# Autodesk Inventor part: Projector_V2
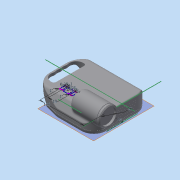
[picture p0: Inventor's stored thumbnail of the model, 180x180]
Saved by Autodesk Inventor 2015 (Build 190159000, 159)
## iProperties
Created: 2013-06
Part Number: Projector_V2
Material: 一般
Document SubType Name: Modeling
Designer: 3214325
Density: 1 g/cm^3
Appearance: Default
Author: 3214325
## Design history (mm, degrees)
sketch "Sketch1"
  geometry: L1 (66, -150)-(-66, -150); L2 (-66, -150)-(-66, 0); L3 (-66, 0)-(66, 0); L4 (66, 0)-(66, -150); L5 (92.4, 0)-(-92.4, 0) reference; L6 (0, -180)-(0, 30) reference; 1 further point
  constraints: 8 end point, 2 parallel, 1 collinear, 1 horizontal, 1 perpendicular, 1 other
  dimensions: "d0" = 132 distance of L2.end L3.end; "d1" = 150 distance of L1.end L2.end
extrude "Extrusion1" new body sketch "Sketch1" distance "d2" = 2; taper "d3" = 0 deg
sketch "Sketch2"
  geometry: L1 (66, -150)-(-66, -150) reference; L2 (66, 0)-(66, -150) reference; L3 (-66, 0)-(66, 0) reference; L4 (-66, -150)-(-66, 0) reference; L5 (92.4, 0)-(-92.4, 0) reference; L6 (-66, -88)-(-49.387, -150); L7 (0, -180)-(0, 30) reference; L8 (66, -88)-(49.387, -150); L9 (-66, -88)-(-66, -150); L10 (-66, -150)-(-49.387, -150); L11 (49.387, -150)-(66, -150); L12 (66, -150)-(66, -88); 1 further point
  constraints: 12 end point, 4 point on line, 2 horizontal, 2 vertical
  dimensions: "d4" = 88 distance from line of L6.start L5; "d5" = 15 deg angle of L6 L4; "d7" = 88 distance from line of L8.start L5; "d8" = 15 deg angle of L8 L2
extrude "Extrusion2" cut sketch "Sketch2" distance "d9" = 2; taper "d10" = 0 deg
fillet "Fillet1" dims "d11" = 30
fillet "Fillet2" dims "d12" = 30
fillet "Fillet3" dims "d13" = 40
sketch "Sketch3"
  geometry: L1 (-18.694, -150)-(18.694, -150) reference; L2 (57.331, -120.353)-(64.978, -91.815) reference; L3 (66, -84.05)-(66, -30) reference; L4 (36, 0)-(-36, 0) reference; L5 (-66, -30)-(-66, -84.05) reference; L6 (-64.978, -91.815)-(-57.331, -120.353) reference; A1 r 40 centre (-18.694, -110) between (-57.331, -120.353) and (-18.694, -150) reference; A2 r 40 centre (18.694, -110) between (18.694, -150) and (57.331, -120.353) reference; A3 r 30 centre (36, -84.05) between (64.978, -91.815) and (66, -84.05) reference; A4 r 30 centre (36, -30) between (66, -30) and (36, 0) reference; A5 r 30 centre (-36, -30) between (-36, 0) and (-66, -30) reference; A6 r 30 centre (-36, -84.05) between (-66, -84.05) and (-64.978, -91.815) reference; 1 further point
extrude "Extrusion3" join sketch "Sketch3" distance "d14" = 5; taper "d15" = -10 deg
sketch "Sketch4"
  geometry: L1 (-18.694, 150)-(18.694, 150) reference; L2 (-27, 145)-(27, 145); L3 (33, 139)-(33, 128); L4 (27, 122)-(-27, 122); L5 (-33, 128)-(-33, 139); L6 (0, 180)-(0, -30) reference; A1 r 6 centre (-27, 139) between (-27, 145) and (-33, 139); A2 r 6 centre (-27, 128) between (-33, 128) and (-27, 122); A3 r 6 centre (27, 128) between (27, 122) and (33, 128); A4 r 6 centre (27, 139) between (33, 139) and (27, 145); 4 further points
  constraints: 8 end point, 8 point on circle, 8 tangent, 6 point on line, 4 centre point, 3 equal radius, 2 parallel, 1 horizontal, 1 perpendicular, 1 other
  dimensions: "d16" = 66 distance of point (33, 122) point (-33, 122); "d17" = 23 distance of point (33, 145) point (33, 122); "d18" = 5 distance between parallel lines of L2 L1; "d19" = 6 radius of A1
extrude "Extrusion4" cut sketch "Sketch4" distance "d20" = 15; taper "d21" = 0 deg
sketch "Sketch5"
  geometry: L1 (-33, 128)-(-33, 139) reference; L2 (-27, 145)-(27, 145) reference; L3 (33, 139)-(33, 128) reference; L4 (27, 122)-(-27, 122) reference; L5 (-57.331, 120.353)-(-64.978, 91.815) reference; L6 (-66, 30)-(-66, 84.05) reference; L7 (36, 0)-(-36, 0) reference; L8 (66, 84.05)-(66, 30) reference; L9 (64.978, 91.815)-(57.331, 120.353) reference; L10 (-18.694, 150)-(18.694, 150) reference; L11 (56.365, 120.094)-(64.012, 91.556); L12 (65, 84.05)-(65, 30); L13 (36, 1)-(-36, 1); L14 (-65, 30)-(-65, 84.05); L15 (-64.012, 91.556)-(-56.365, 120.094); L16 (-18.694, 149)-(18.694, 149); A1 r 6 centre (-27, 128) between (-33, 128) and (-27, 122) reference; A2 r 6 centre (-27, 139) between (-27, 145) and (-33, 139) reference; A3 r 6 centre (27, 139) between (33, 139) and (27, 145) reference; A4 r 6 centre (27, 128) between (27, 122) and (33, 128) reference; A5 r 40 centre (-18.694, 110) between (-18.694, 150) and (-57.331, 120.353) reference; A6 r 30 centre (-36, 84.05) between (-64.978, 91.815) and (-66, 84.05) reference; A7 r 30 centre (-36, 30) between (-66, 30) and (-36, 0) reference; A8 r 30 centre (36, 30) between (36, 0) and (66, 30) reference; A9 r 30 centre (36, 84.05) between (66, 84.05) and (64.978, 91.815) reference; A10 r 40 centre (18.694, 110) between (57.331, 120.353) and (18.694, 150) reference; A11 r 39 centre (18.694, 110) between (56.365, 120.094) and (18.694, 149); A12 r 29 centre (36, 84.05) between (65, 84.05) and (64.012, 91.556); A13 r 29 centre (36, 30) between (36, 1) and (65, 30); A14 r 29 centre (-36, 30) between (-65, 30) and (-36, 1); A15 r 29 centre (-36, 84.05) between (-64.012, 91.556) and (-65, 84.05); A16 r 39 centre (-18.694, 110) between (-18.694, 149) and (-56.365, 120.094); 1 further point
  constraints: 12 end point, 12 point on circle, 6 centre point, 11 other
  dimensions: "d28" = 1 distance between parallel lines of L8 L12
extrude "Extrusion5" join sketch "Sketch5" distance "d22" = 0.3; taper "d23" = 0 deg
sketch "Sketch6"
  geometry: L1 (-33, 128)-(-33, 139) reference; L2 (-27, 145)-(27, 145) reference; L3 (33, 139)-(33, 128) reference; L4 (27, 122)-(-27, 122) reference; L5 (18.694, 149)-(-18.694, 149) reference; L6 (-56.365, 120.094)-(-64.012, 91.556) reference; L7 (-65, 84.05)-(-65, 30) reference; L8 (-36, 1)-(36, 1) reference; L9 (65, 30)-(65, 84.05) reference; L10 (64.012, 91.556)-(56.365, 120.094) reference; L11 (0, 206.201)-(0, -40.207) reference; L12 (-99.409, 0)-(99.409, 0) reference; L13 (-39, 171)-(39, 171); L14 (39, 171)-(39, 121); L15 (39, 121)-(-39, 121); L16 (-39, 121)-(-39, 171); A1 r 6 centre (-27, 139) between (-27, 145) and (-33, 139) reference; A2 r 6 centre (27, 139) between (33, 139) and (27, 145) reference; A3 r 6 centre (27, 128) between (27, 122) and (33, 128) reference; A4 r 6 centre (-27, 128) between (-33, 128) and (-27, 122) reference; A5 r 39 centre (18.694, 110) between (56.365, 120.094) and (18.694, 149) reference; A6 r 39 centre (-18.694, 110) between (-18.694, 149) and (-56.365, 120.094) reference; A7 r 29 centre (-36, 84.05) between (-64.012, 91.556) and (-65, 84.05) reference; A8 r 29 centre (-36, 30) between (-65, 30) and (-36, 1) reference; A9 r 29 centre (36, 30) between (36, 1) and (65, 30) reference; A10 r 29 centre (36, 84.05) between (65, 84.05) and (64.012, 91.556) reference
  constraints: 8 end point, 2 parallel, 1 horizontal, 1 perpendicular, 1 other
  dimensions: "d29" = 78 distance of L14.end L15.end; "d30" = 50 distance of L13.end L14.end; "d31" = 121 distance between parallel lines of L12 L15
extrude "Extrusion6" cut sketch "Sketch6" stored distance "d32" = 0.3; taper "d33" = 0 deg
fillet "Fillet4" dims "d34" = 6
fillet "Fillet5" dims "d35" = 2
sketch "Sketch7"
  geometry: L1 (-56.365, 120.094)-(-64.012, 91.556) reference; L2 (-65, 84.05)-(-65, 30) reference; L3 (-36, 1)-(36, 1) reference; L4 (65, 30)-(65, 84.05) reference; L5 (64.012, 91.556)-(56.365, 120.094) reference; L6 (39, 143.297)-(39, 121) reference; L7 (39, 121)-(-39, 121) reference; L8 (-39, 121)-(-39, 143.297) reference; L9 (66, 84.05)-(66, 30); L10 (36, 0)-(-36, 0); L11 (-66, 30)-(-66, 84.05); L12 (-64.978, 91.815)-(-57.331, 120.353); L13 (-38, 139.52)-(-38, 127); L14 (-33, 122)-(33, 122); L15 (38, 127)-(38, 139.52); L16 (57.331, 120.353)-(64.978, 91.815); A1 r 2 centre (-41, 139.52) between (-39, 139.52) and (-42.206, 141.116) reference; A2 r 39 centre (-18.694, 110) between (-39, 143.297) and (-56.365, 120.094) reference; A3 r 29 centre (-36, 84.05) between (-64.012, 91.556) and (-65, 84.05) reference; A4 r 29 centre (-36, 30) between (-65, 30) and (-36, 1) reference; A5 r 29 centre (36, 30) between (36, 1) and (65, 30) reference; A6 r 29 centre (36, 84.05) between (65, 84.05) and (64.012, 91.556) reference; A7 r 39 centre (18.694, 110) between (56.365, 120.094) and (39, 143.297) reference; A8 r 2 centre (41, 139.52) between (42.206, 141.116) and (39, 139.52) reference; A9 r 6 centre (33, 127) between (33, 121) and (39, 127) reference; A10 r 6 centre (-33, 127) between (-39, 127) and (-33, 121) reference; A11 r 30 centre (36, 30) between (36, 0) and (66, 30); A12 r 30 centre (-36, 30) between (-66, 30) and (-36, 0); A13 r 30 centre (-36, 84.05) between (-64.978, 91.815) and (-66, 84.05); A14 r 40 centre (-18.694, 110) between (-42.809, 141.914) and (-57.331, 120.353); A15 r 3 centre (-41, 139.52) between (-38, 139.52) and (-42.809, 141.914); A16 r 5 centre (-33, 127) between (-38, 127) and (-33, 122); A17 r 5 centre (33, 127) between (33, 122) and (38, 127); A18 r 3 centre (41, 139.52) between (42.809, 141.914) and (38, 139.52); A19 r 40 centre (18.694, 110) between (57.331, 120.353) and (42.809, 141.914); A20 r 30 centre (36, 84.05) between (66, 84.05) and (64.978, 91.815); 1 further point
  constraints: 20 point on circle, 16 end point, 10 centre point, 17 other
  dimensions: "d36" = 1 distance between parallel lines of L4 L9
extrude "Extrusion7" join sketch "Sketch7" distance "d37" = 30.7; taper "d38" = 0 deg
sketch "Sketch8"
  geometry: L1 (66, 31)-(64.978, 31) reference; L2 (64.978, 31)-(57.331, 31) reference; L3 (57.331, 31)-(42.809, 31) reference; L4 (42.809, 31)-(38, 31) reference; L5 (38, 31)-(33, 31) reference; L6 (33, 31)-(-33, 31) reference; L7 (-33, 31)-(-38, 31) reference; L8 (-38, 31)-(-42.809, 31) reference; L9 (-42.809, 31)-(-57.331, 31) reference; L10 (-57.331, 31)-(-64.978, 31) reference; L11 (-64.978, 31)-(-66, 31) reference; L12 (-66, 31)-(-36, 31) reference; L13 (-36, 31)-(36, 31) reference; L14 (36, 31)-(66, 31) reference; L15 (-66, 0.3)-(-66, 31) reference; L16 (-66, 0.3)-(-66, 31) reference; L17 (66, 0.3)-(66, 31) reference; L18 (66, 0.3)-(66, 31) reference; L19 (-66, 31)-(-66, 11.006); L20 (-66, 11.006)-(-52, 31); L21 (-52, 31)-(-66, 31); L22 (66, 31)-(66, 11.006); L23 (66, 11.006)-(52, 31); L24 (52, 31)-(66, 31); 1 further point
  constraints: 12 end point, 4 point on line, 2 horizontal
  dimensions: "d39" = 14 distance from line of L20.end L15; "d40" = 14 distance from line of L23.end L17; "d41" = 55 deg angle of L6 L20; "d42" = 55 deg angle of L6 L23
extrude "Extrusion8" cut sketch "Sketch8" distance "d43" = 200; taper "d44" = 0 deg
sketch "Sketch9"
  geometry: L1 (-8.6, 0)-(37.6, 0) reference; L2 (0, -180)-(0, 30) reference; L3 (0, -150)-(-2, -150) reference; L4 (31, -132.152)-(31, -4.623) reference; L5 (31, -116)-(0.386, -150); L6 (0.386, -150)-(31, -150); L7 (31, -150)-(31, -116); L8 (6, -143.765)-(6, -150); 1 further point
  constraints: 8 end point, 3 point on line, 2 vertical, 1 collinear, 1 horizontal
  dimensions: "d45" = 34 distance from line of L5.start L6; "d47" = 42 deg angle of L5 L7; "d51" = 25 distance between parallel lines of L7 L8
extrude "Extrusion9" cut sketch "Sketch9" stored distance "d49" = 200; taper "d50" = 0 deg
fillet "Fillet6" dims "d52" = 10
fillet "Fillet7" dims "d53" = 8
fillet "Fillet8" dims "d54" = 3
sketch "Sketch10"
  geometry: L1 (-66, 0.3)-(-66, 11.006) reference; L2 (-66, 0.3)-(-66, 11.006) reference; L3 (66, 0.3)-(36, 0.3) reference; L4 (36, 0.3)-(-36, 0.3) reference; L5 (-36, 0.3)-(-66, 0.3) reference; L6 (-66, 0.3)-(-64.978, 0.3) reference; L7 (-64.978, 0.3)-(-57.331, 0.3) reference; L8 (-57.331, 0.3)-(-42.809, 0.3) reference; L9 (-42.809, 0.3)-(-40.334, 0.3) reference; L10 (-38, 0.3)-(-33, 0.3) reference; L11 (-33, 0.3)-(33, 0.3) reference; L12 (33, 0.3)-(38, 0.3) reference; L13 (38, 0.3)-(39, 0.3) reference; L14 (42.809, 0.3)-(57.331, 0.3) reference; L15 (57.331, 0.3)-(64.978, 0.3) reference; L16 (64.978, 0.3)-(66, 0.3) reference; L17 (64.012, 0.3)-(56.365, 0.3) reference; L18 (56.365, 0.3)-(40.334, 0.3) reference; L19 (39, 0.3)-(-39, 0.3) reference; L20 (-40.334, 0.3)-(-56.365, 0.3) reference; L21 (-56.365, 0.3)-(-64.012, 0.3) reference; L22 (-64.012, 0.3)-(-65, 0.3) reference; L23 (-65, 0.3)-(-36, 0.3) reference; L24 (-36, 0.3)-(36, 0.3) reference; L25 (36, 0.3)-(65, 0.3) reference; L26 (65, 0.3)-(64.012, 0.3) reference; L27 (-39, 0.3)-(-38, 0.3) reference; L28 (40.334, 0.3)-(42.809, 0.3) reference; C1 r 22 at (-44, 33); 1 further point
  constraints: 1 centre point
  dimensions: "d55" = 44 diameter of C1; "d56" = 22 distance from line of C1.centre L1; "d57" = 32.7 distance from line of C1.centre L19
extrude "Extrusion10" new body sketch "Sketch10" distance "d58" = 60; taper "d59" = 0 deg
sketch "Sketch11"
  geometry: C1 r 22 at (0, 0) reference; 1 further point
extrude "Extrusion11" join sketch "Sketch11" distance "d60" = 6; taper "d61" = 0 deg
sketch "Sketch12"
  geometry: C1 r 22 at (0, 0) reference; C2 r 21 at (0, 0); 1 further point
  constraints: 1 centre point
  dimensions: "d62" = 1 radial gap between concentric circles of C1 C2
extrude "Extrusion12" join sketch "Sketch12" distance "d63" = 1; taper "d64" = 0 deg
sketch "Sketch13"
  geometry: C1 r 21 at (0, 0) reference; C2 r 22 at (0, 0); 1 further point
  constraints: 1 centre point
  dimensions: "d65" = 44 diameter of C2
extrude "Extrusion13" join sketch "Sketch13" distance "d67" = 6; taper "d68" = 0 deg
sketch "Sketch14"
  geometry: C1 r 22 at (0, 0) reference; C2 r 18 at (0, 0); 1 further point
  constraints: 1 centre point
  dimensions: "d69" = 36 diameter of C2
extrude "Extrusion14" cut sketch "Sketch14" distance "d71" = 5; taper "d72" = 0 deg
fillet "Fillet9" dims "d73" = 12
chamfer "Chamfer1" distance "d74" = 2; stored, may be unused: second distance "d75" = 2, angle "d76" = 45 deg
combine "Combine1"
  body "Solid2"
fillet "Fillet10" dims "d77" = 6
sketch "Sketch15"
  geometry: L1 (-42, 104)-(-31, 104); L2 (-30, 103)-(-30, 100); L3 (-31, 99)-(-42, 99); L4 (-43, 100)-(-43, 103); L5 (-42, 80)-(-31, 80); L6 (-30, 79)-(-30, 76); L7 (-31, 75)-(-42, 75); L8 (-43, 76)-(-43, 79); L9 (-92.4, 0)-(92.4, 0) reference; L10 (0, 180)-(0, -30) reference; L11 (-66, 30)-(-66, 84.05) reference; L12 (-36.5, 104)-(-36.5, 75); L13 (-31, 104.25)-(-42, 104.25); L14 (-43.25, 103)-(-43.25, 100); L15 (-42, 98.75)-(-31, 98.75); L16 (-29.75, 100)-(-29.75, 103); L17 (-31, 80.25)-(-42, 80.25); L18 (-43.25, 79)-(-43.25, 76); L19 (-42, 74.75)-(-31, 74.75); L20 (-29.75, 76)-(-29.75, 79); L21 (-66, 30)-(-66, 84.05) reference; A1 r 1 centre (-42, 103) between (-42, 104) and (-43, 103); A2 r 1 centre (-42, 100) between (-43, 100) and (-42, 99); A3 r 1 centre (-31, 103) between (-30, 103) and (-31, 104); A4 r 1 centre (-31, 100) between (-31, 99) and (-30, 100); A5 r 1 centre (-42, 79) between (-42, 80) and (-43, 79); A6 r 1 centre (-31, 79) between (-30, 79) and (-31, 80); A7 r 1 centre (-31, 76) between (-31, 75) and (-30, 76); A8 r 1 centre (-42, 76) between (-43, 76) and (-42, 75); A9 r 1.25 centre (-42, 103) between (-42, 104.25) and (-43.25, 103); A10 r 1.25 centre (-42, 100) between (-43.25, 100) and (-42, 98.75); A11 r 1.25 centre (-31, 100) between (-31, 98.75) and (-29.75, 100); A12 r 1.25 centre (-31, 103) between (-29.75, 103) and (-31, 104.25); A13 r 1.25 centre (-42, 79) between (-42, 80.25) and (-43.25, 79); A14 r 1.25 centre (-42, 76) between (-43.25, 76) and (-42, 74.75); A15 r 1.25 centre (-31, 76) between (-31, 74.75) and (-29.75, 76); A16 r 1.25 centre (-31, 79) between (-29.75, 79) and (-31, 80.25); 6 further points
  constraints: 34 end point, 32 point on circle, 16 centre point, 16 tangent, 10 point on line, 8 parallel, 6 equal radius, 4 perpendicular, 2 horizontal, 2 midpoint, 1 collinear, 14 other
  dimensions: "d78" = 13 distance of point (-30, 99) point (-43, 99); "d79" = 5 distance of point (-30, 104) point (-30, 99); "d80" = 5 distance of point (-30, 80) point (-30, 75); "d81" = 104 distance between parallel lines of L1 L9; "d82" = 19 distance between parallel lines of L5 L3; "d84" = 1 radius of A1; "d85" = 1 radius of A5; "d86" = 0.25 distance between parallel lines of L16 L2; "d87" = 0.25 distance between parallel lines of L20 L6
extrude "Extrusion15" cut sketch "Sketch15" distance "d88" = 5; taper "d89" = 0 deg
sketch "Sketch16"
  geometry: L1 (-92.4, 0)-(92.4, 0) reference; L2 (0, -180)-(0, 30) reference; C1 r 7.5 at (-41, -27.5); C2 r 7.5 at (41, -27.5); C3 r 7.5 at (-41, -112.5); C4 r 7.5 at (41, -112.5); 1 further point
  constraints: 4 centre point, 2 horizontal alignment, 2 vertical alignment, 1 symmetric about line
  dimensions: "d99" = 15 diameter of C1; "d100" = 15 diameter of C2; "d101" = 15 diameter of C3; "d102" = 15 diameter of C4; "d103" = 20 distance edge to line of C1 L1; "d104" = 100 dimension on C3 C1; "d105" = 97 dimension on C2 C1
extrude "Extrusion18" join sketch "Sketch16" distance "d106" = 5; taper "d107" = 0 deg
fillet "Fillet12" dims "d108" = 1
sketch "Sketch17"
  geometry: L1 (72, 0)-(0, 0) reference; L2 (25, 7)-(68, 7); L3 (69, 6)-(69, 6); L4 (68, 5)-(25, 5); L5 (24, 6)-(24, 6); L6 (46.5, 5)-(46.5, 7); C1 r 18 at (-8, 32.7) reference; A1 r 1 centre (25, 6) between (25, 7) and (24, 6); A2 r 1 centre (25, 6) between (24, 6) and (25, 5); A3 r 1 centre (68, 6) between (68, 5) and (69, 6); A4 r 1 centre (68, 6) between (69, 6) and (68, 7); 4 further points
  constraints: 10 end point, 8 point on circle, 8 tangent, 6 point on line, 4 centre point, 3 equal radius, 2 midpoint, 2 parallel, 1 horizontal, 1 perpendicular
  dimensions: "d109" = 45 distance of point (69, 5) point (24, 5); "d110" = 2 distance of point (69, 7) point (69, 5); "d111" = 1 radius of A1; "d113" = 5 distance between parallel lines of L4 L1; "d119" = 54.5 horizontal distance of C1.centre L6.start
extrude "Extrusion19" join sketch "Sketch17" distance "d114" = 0.1; taper "d115" = 0 deg
pattern_linear "Rectangular Pattern1" dims "d118" = 5
sketch "Sketch19"
  geometry: L1 (-57.331, 120.353)-(-64.978, 91.815) reference; L2 (-18.694, 150)-(18.694, 150) reference; L3 (64.978, 91.815)-(57.331, 120.353) reference; L4 (-66, 84.05)-(66, 84.05); L5 (-33, 139)-(-33, 128) reference; L6 (-27, 122)-(27, 122) reference; L7 (33, 128)-(33, 139) reference; L8 (27, 145)-(-27, 145) reference; A1 r 30 centre (-36, 84.05) between (-64.978, 91.815) and (-66, 84.05) reference; A2 r 40 centre (-18.694, 110) between (-18.694, 150) and (-57.331, 120.353) reference; A3 r 40 centre (18.694, 110) between (57.331, 120.353) and (18.694, 150) reference; A4 r 30 centre (36, 84.05) between (66, 84.05) and (64.978, 91.815) reference; A5 r 6 centre (-27, 139) between (-27, 145) and (-33, 139) reference; A6 r 6 centre (-27, 128) between (-33, 128) and (-27, 122) reference; A7 r 6 centre (27, 128) between (27, 122) and (33, 128) reference; A8 r 6 centre (27, 139) between (33, 139) and (27, 145) reference; 1 further point
  constraints: 2 end point, 1 parallel
extrude "Extrusion20" join sketch "Sketch19" distance "d120" = 7; taper "d121" = 0 deg
delete_face "Delete Face1"
delete_face "Delete Face2"
sketch "Sketch20"
  geometry: L1 (6, 23.7)-(0, 23.7) reference; L2 (-41.343, -60.416)-(107.343, -60.416); L3 (107.343, -60.416)-(107.343, 23.7); L4 (107.343, 23.7)-(-41.343, 23.7); L5 (-41.343, 23.7)-(-41.343, -60.416); L6 (-41.343, -60.416)-(107.343, 23.7); L7 (107.343, -60.416)-(-41.343, 23.7); L8 (-6, -0.3)-(72, -0.3) reference; 4 further points
  constraints: 12 end point, 4 midpoint, 2 parallel, 1 collinear, 1 horizontal, 1 perpendicular, 1 vertical alignment
extrude "Extrusion21" cut sketch "Sketch20" distance "d122" = 55.75; taper "d123" = 0 deg
delete_face "Delete Face3"
delete_face "Delete Face4"
chamfer "Chamfer2" distance "d124" = 23; stored, may be unused: second distance "d125" = 2, angle "d126" = 45 deg
sketch "Sketch21"
  geometry: L1 (1, -122)-(0.3, -122) reference; L2 (1, -122)-(7, -128) reference; L3 (7, -128)-(18, -139) reference; L4 (24, -145)-(18, -139) reference; L5 (24, -150)-(24, -145) reference; L6 (0.3, -122)-(24, -145.7); 1 further point
  constraints: 2 end point, 1 parallel, 1 point on line
extrude "Extrusion22" join sketch "Sketch21" stored distance "d127" = 125.25; taper "d128" = 0 deg
delete_face "Delete Face5"
delete_face "Delete Face6"
delete_face "Delete Face7"
delete_face "Delete Face8"
fillet "Fillet13" dims "d129" = 16
feature "Move Face1"
feature "Move Face2"
sketch "Sketch23"
  geometry: L1 (56.694, -21)-(56.694, -22) reference; L2 (50.694, -28)-(-13.306, -28) reference; L3 (-19.306, -22)-(-19.306, -21) reference; L4 (-3.306, -5)-(40.694, -5) reference; L5 (70.694, -145.377)-(70.694, -17.848) reference; L6 (-3.306, -5)-(40.694, -5); A1 r 6 centre (50.694, -22) between (50.694, -28) and (56.694, -22) reference; A2 r 6 centre (-13.306, -22) between (-19.306, -22) and (-13.306, -28) reference; A3 r 16 centre (-3.306, -21) between (-3.306, -5) and (-19.306, -21) reference; A4 r 16 centre (40.694, -21) between (56.694, -21) and (40.694, -5) reference; A5 r 16 centre (25.694, -21) between (33.194, -6.867) and (18.694, -6.613); A6 r 16 centre (11.694, -21) between (18.694, -6.613) and (4.194, -6.867); A7 r 16 centre (40.694, -21) between (56.682, -21.62) and (56.694, -21); A8 r 16 centre (40.694, -21) between (40.694, -5) and (33.194, -6.867); A9 r 16 centre (-3.306, -21) between (4.194, -6.867) and (-3.306, -5); A10 r 16 centre (-3.306, -21) between (-19.306, -21) and (-19.1, -23.558); 3 further points
  constraints: 15 point on circle, 6 centre point, 6 tangent, 4 end point, 2 coincident, 2 midpoint, 1 horizontal alignment, 1 perpendicular, 1 vertical alignment
  dimensions: "d145" = 16 radius of A6; "d195" = 15 distance of A9.centre A6.centre
extrude "Extrusion24" join sketch "Sketch23" stored distance "d147" = 125.25; taper "d148" = 0 deg
fillet "Fillet14" dims "d149" = 10
sketch "Sketch24"
  geometry: L1 (0.3, -120.353)-(0.3, -122) reference; L2 (24, -150)-(24, -145.7) reference; L3 (0.3, -122)-(24, -141.887); L4 (24, -141.887)-(24, -150); L5 (0.3, -122)-(24, -150); L6 (31, -122)-(0.3, -122) reference; 1 further point
  constraints: 6 end point, 1 collinear
  dimensions: "d150" = 40 deg angle of L3 L6
extrude "Extrusion25" cut sketch "Sketch24" stored distance "d151" = 125.25; taper "d152" = 0 deg
fillet "Fillet15" dims "d153" = 5
delete_face "Delete Face9"
fillet "Fillet16" dims "d154" = 5
sketch "Sketch25"
  geometry: L1 (-11.306, -50)-(-11.306, -47) reference; L2 (-23.306, -51)-(-12.306, -51) reference; L3 (-24.306, -47)-(-24.306, -50) reference; L4 (-23.306, -67)-(-12.306, -67); L5 (-11.306, -66)-(-11.306, -55); L6 (-12.306, -54)-(-23.306, -54); L7 (-24.306, -55)-(-24.306, -66); L8 (-23.306, -70)-(-12.306, -70) reference; A1 r 1 centre (-12.306, -55) between (-11.306, -55) and (-12.306, -54); A2 r 1 centre (-23.306, -55) between (-23.306, -54) and (-24.306, -55); A3 r 1 centre (-23.306, -66) between (-24.306, -66) and (-23.306, -67); A4 r 1 centre (-12.306, -66) between (-12.306, -67) and (-11.306, -66); 1 further point
  constraints: 8 end point, 8 point on circle, 8 tangent, 4 centre point, 3 equal radius, 2 collinear, 2 parallel, 1 horizontal, 1 perpendicular
  dimensions: "d157" = 3 distance between parallel lines of L4 L8; "d158" = 3 distance between parallel lines of L2 L6 (derived); "d159" = 1 radius of A1
sketch "Sketch26"
  geometry: L1 (-24.306, -66)-(-24.306, -55) reference; L2 (-23.306, -54)-(-12.306, -54) reference; L3 (-11.306, -55)-(-11.306, -66) reference; L4 (-12.306, -67)-(-23.306, -67) reference; L5 (-12.306, -46)-(-23.306, -46) reference; L6 (-11.306, -50)-(-11.306, -47) reference; L7 (-23.306, -51)-(-12.306, -51) reference; L8 (-24.306, -47)-(-24.306, -50) reference; L9 (-11.056, -66)-(-11.056, -55); L10 (-12.306, -53.75)-(-23.306, -53.75); L11 (-24.556, -55)-(-24.556, -66); L12 (-23.306, -67.25)-(-12.306, -67.25); L13 (-12.306, -45.75)-(-23.306, -45.75); L14 (-24.556, -47)-(-24.556, -50); L15 (-23.306, -51.25)-(-12.306, -51.25); L16 (-11.056, -50)-(-11.056, -47); A1 r 1 centre (-23.306, -55) between (-23.306, -54) and (-24.306, -55) reference; A2 r 1 centre (-12.306, -55) between (-11.306, -55) and (-12.306, -54) reference; A3 r 1 centre (-12.306, -66) between (-12.306, -67) and (-11.306, -66) reference; A4 r 1 centre (-23.306, -66) between (-24.306, -66) and (-23.306, -67) reference; A5 r 1 centre (-23.306, -47) between (-23.306, -46) and (-24.306, -47) reference; A6 r 1 centre (-12.306, -47) between (-11.306, -47) and (-12.306, -46) reference; A7 r 1 centre (-12.306, -50) between (-12.306, -51) and (-11.306, -50) reference; A8 r 1 centre (-23.306, -50) between (-24.306, -50) and (-23.306, -51) reference; A9 r 1.25 centre (-12.306, -55) between (-11.056, -55) and (-12.306, -53.75); A10 r 1.25 centre (-23.306, -55) between (-23.306, -53.75) and (-24.556, -55); A11 r 1.25 centre (-23.306, -66) between (-24.556, -66) and (-23.306, -67.25); A12 r 1.25 centre (-12.306, -66) between (-12.306, -67.25) and (-11.056, -66); A13 r 1.25 centre (-12.306, -47) between (-11.056, -47) and (-12.306, -45.75); A14 r 1.25 centre (-23.306, -47) between (-23.306, -45.75) and (-24.556, -47); A15 r 1.25 centre (-23.306, -50) between (-24.556, -50) and (-23.306, -51.25); A16 r 1.25 centre (-12.306, -50) between (-12.306, -51.25) and (-11.056, -50); 1 further point
  constraints: 16 end point, 16 point on circle, 8 centre point, 14 other
  dimensions: "d162" = 0.25 distance between parallel lines of L3 L9; "d163" = 0.25 distance between parallel lines of L6 L16
delete_face "Delete Face10"
sketch "Sketch27"
  geometry: L1 (19.926, 121.118)-(91.926, 121.118) reference; L2 (91.926, 122)-(19.926, 122) reference; C1 r 15 at (55.926, 92); 2 further points
  constraints: 1 centre point, 1 midpoint, 1 vertical alignment
  dimensions: "d166" = 30 diameter of C1; "d170" = 15 distance edge to line of C1 L2
workplane "Work Plane2"
sketch "Sketch28"
  geometry: L1 (0, 0)-(9.192, 9.192); L2 (0.75, 0)-(22.911, 0); A1 r 15 centre (0, 0) between (13.707, 6.092) and (6.092, 13.707) reference; A2 r 15 centre (19.799, 19.799) between (6.092, 13.707) and (13.707, 6.092); 1 further point
  constraints: 5 point on circle, 4 end point, 1 centre point, 1 horizontal, 1 point on line
  dimensions: "d173" = 45 deg angle of L1 L2; "d174" = 2 dimension on A1 A2; "d175" = 15 radius of A2
extrude "Extrusion29" cut sketch "Sketch28" stored distance "d176" = 125.25; taper "d177" = 0 deg
fillet "Fillet17" dims "d181" = 8
fillet "Fillet18" dims "d182" = 3
fillet "Fillet19" dims "d183" = 6
fillet "Fillet20" dims "d184" = 0.5
fillet "Fillet23" dims "d187" = 1
chamfer "Chamfer3" distance "d190" = 5; stored, may be unused: second distance "d191" = 2, angle "d192" = 10 deg
fillet "Fillet26" dims "d193" = 0.5
fillet "Fillet27" dims "d194" = 0.5
workplane "Work Plane1"
split "Split1"
extrude "Extrusion30" join sketch "Sketch15" stored distance "d197" = 10; taper "d198" = 0 deg
body "Solid1"
node "Projected Loop1"
node "Projected Loop2"
node "Projected Loop3"
node "Projected Loop4"
node "Projected Loop5"
node "Projected Loop6"
node "Projected Loop7"
node "Projected Loop8"
node "Projected Loop9"
body "Solid3"
body "Solid4"
other parameters: "d142" = 1, "d144" = 16, "d196" = 0
